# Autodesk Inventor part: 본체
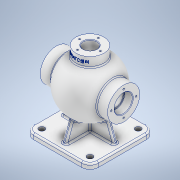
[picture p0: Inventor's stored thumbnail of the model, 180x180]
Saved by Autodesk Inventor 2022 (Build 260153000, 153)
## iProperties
Created: 2024-04
Part Number: 본체
Material: 알루미늄 6061
Document SubType Name: Modeling
Designer: Admin
Mass: 1526.53 g
Surface Area: 1174.37 cm^2
Volume: 565.38 cm^3
Density: 2.7 g/cm^3
Appearance: 알루미늄 - 평지
Author: Admin
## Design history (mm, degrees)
sketch "스케치1"
  geometry: L1 (-75.6, 0)-(75.6, 0) reference; L2 (0, -10.8)-(0, 64.8) reference; L3 (-54, 0)-(54, 0); A1 r 54 centre (0, 0) between (54, 0) and (-54, 0); 1 further point
  constraints: 2 end point, 2 point on circle, 1 centre point, 1 coincident, 1 horizontal, 1 symmetric about line
  dimensions: "d7" = 54 radius of A1; "d11" = 108 distance of L3.start L3.end
revolve "회전1" sketch "스케치1" stored, may be unused: angle "d9" = 90 deg
node "작업 평면2"
sketch "스케치2"
  geometry: C1 r 31 at (0, 0); 1 further point
  constraints: 1 centre point, 1 coincident
  dimensions: "d13" = 62 diameter of C1
extrude "돌출1" join sketch "스케치2" stored distance "d14" = 10; taper "d15" = 0 deg
node "작업 평면3"
sketch "스케치3"
  geometry: L1 (62.5, -62.5)-(-62.5, -62.5); L2 (-62.5, -62.5)-(-62.5, 62.5); L3 (-62.5, 62.5)-(62.5, 62.5); L4 (62.5, 62.5)-(62.5, -62.5); L5 (62.5, -62.5)-(-62.5, 62.5); L6 (-62.5, -62.5)-(62.5, 62.5); 1 further point
  constraints: 12 end point, 2 midpoint, 2 parallel, 1 horizontal, 1 perpendicular
  dimensions: "d17" = 125 distance of L2.end L3.end; "d18" = 125 distance of L1.end L2.end
extrude "돌출2" join sketch "스케치3" distance "d19" = 10; taper "d20" = 0 deg
sketch "스케치4"
  geometry: L1 (-112.8, 0)-(81.8, 0) reference; L2 (0, -87.5)-(0, 87.5) reference; L3 (-75, -50.5)-(0, -23.202); L4 (0, -23.202)-(0, 23.202); L5 (0, 23.202)-(-75, 50.5); L6 (-75, 62.5)-(-75, -62.5) reference; L7 (-85, -62.5)-(-75, -62.5) reference; L8 (-75, -50.5)-(-75, 50.5); 1 further point
  constraints: 8 end point, 2 point on line, 1 collinear, 1 midpoint, 1 vertical, 1 other
  dimensions: "d21" = 12 distance of L3.start L6.end; "d23" = 20 deg angle of L7 L3
extrude "돌출3" join sketch "스케치4" stored distance "d24" = 8; taper "d25" = 0 deg
sketch "스케치5"
  geometry: L1 (-91, 0)-(91, 0) reference; L2 (0, -112.8)-(0, 81.8) reference; L3 (50.5, -75)-(23.202, 0); L4 (23.202, 0)-(-23.202, 0); L5 (-23.202, 0)-(-50.5, -75); L6 (-62.5, -75)-(62.5, -75) reference; L7 (62.5, -85)-(62.5, -75) reference; L8 (50.5, -75)-(-50.5, -75); 1 further point
  constraints: 8 end point, 2 point on line, 1 collinear, 1 horizontal, 1 midpoint, 1 other
  dimensions: "d26" = 20 deg angle of L7 L3; "d27" = 12 distance of L6.end L3.start
extrude "돌출4" join sketch "스케치5" stored distance "d28" = 8; taper "d29" = 0 deg
sketch "스케치6"
  geometry: L1 (-91, 0)-(91, 0) reference; L2 (0, -112.8)-(0, 81.8) reference; L3 (44, 0)-(-44, 0); L4 (-44.215, -31)-(-44.215, 31) reference; A1 r 44 centre (0, 0) between (44, 0) and (-44, 0); 1 further point
  constraints: 2 end point, 2 point on circle, 2 point on line, 1 centre point, 1 coincident, 1 perpendicular, 1 symmetric about line
  dimensions: "d30" = 44 radius of A1
revolve "회전2" sketch "스케치6" stored, may be unused: angle "d31" = 90 deg
sketch "스케치7"
  geometry: C1 r 17.5 at (0, 0); 1 further point
  constraints: 1 centre point, 1 coincident
  dimensions: "d32" = 35 diameter of C1
extrude "돌출5" cut sketch "스케치7" distance "d33" = 16; taper "d34" = 0 deg
sketch "스케치8"
  geometry: C1 r 15 at (0, 0); 1 further point
  constraints: 1 centre point, 1 coincident
  dimensions: "d35" = 30 diameter of C1
extrude "돌출6" cut sketch "스케치8" stored distance "d36" = 16; taper "d37" = 0 deg
node "작업 평면7"
sketch "스케치9"
  geometry: C1 r 27 at (0, 0); 1 further point
  constraints: 1 centre point, 1 coincident
  dimensions: "d41" = 54 diameter of C1
extrude "돌출7" join sketch "스케치9" stored distance "d42" = 10; taper "d43" = 0 deg
sketch "스케치10"
  geometry: C1 r 13 at (0, 0); 1 further point
  constraints: 1 centre point, 1 coincident
  dimensions: "d44" = 26 diameter of C1
extrude "돌출8" cut sketch "스케치10" stored distance "d45" = 10; taper "d46" = 0 deg
sketch "스케치11"
  geometry: L1 (-91, 0)-(91, 0) reference; L2 (-4, -50.5)-(-4, -4) reference; L3 (-4, 37.329)-(-4, 4) reference; 7 further points
  constraints: 4 point on line, 1 horizontal alignment, 1 symmetric about line, 1 other
  dimensions: "d47" = 40 distance of point (-4, 20) point (-4, -20); "d48" = 40 distance of point (20, 0) point (-20, 0)
hole "구멍1" sketch "스케치11" at (-4, -20), (20, 0), (-4, 20), (-20, 0) diameter "d49" = 3.242; stored, may be unused: countersink angle "d53" = 90 deg, drill point angle "d55" = 118 deg; dims "d50" = 9, "d51" = 4, "d52" = 2, "d54" = 11
sketch "스케치12"
  geometry: L1 (0, -115)-(0, 95) reference; L2 (87.5, 0)-(-87.5, 0) reference; 5 further points
  constraints: 4 point on line, 2 symmetric about line
  dimensions: "d56" = 48 distance of point (24, 0) point (-24, 0); "d57" = 48 distance of point (0, 24) point (0, -24)
hole "구멍2" sketch "스케치12" at (-24, 0), (0, -24), (24, 0), (0, 24) diameter "d58" = 3.242; stored, may be unused: countersink angle "d62" = 90 deg, drill point angle "d64" = 118 deg; dims "d59" = 12, "d60" = 4, "d61" = 2, "d63" = 15
fillet "모깎기1" dims "d65" = 16
fillet "모깎기2" dims "d66" = 3
sketch "스케치13"
  geometry: L1 (-91, 0)-(91, 0) reference; L2 (46.5, 62.5)-(-46.5, 62.5) reference; L3 (62.5, -46.5)-(62.5, 46.5) reference; L4 (-46.5, -62.5)-(46.5, -62.5) reference; L5 (-62.5, 46.5)-(-62.5, -46.5) reference; L6 (0, 62.5)-(0, -62.5); A1 r 16 centre (-46.5, 46.5) between (-46.5, 62.5) and (-62.5, 46.5) reference; A2 r 16 centre (46.5, 46.5) between (62.5, 46.5) and (46.5, 62.5) reference; A3 r 16 centre (46.5, -46.5) between (46.5, -62.5) and (62.5, -46.5) reference; A4 r 16 centre (-46.5, -46.5) between (-62.5, -46.5) and (-46.5, -62.5) reference; 5 further points
  constraints: 4 coincident, 2 end point, 2 midpoint
hole "구멍3" sketch "스케치13" at (-46.5, 46.5), (46.5, 46.5), (46.5, -46.5), (-46.5, -46.5) diameter "d71" = 11; stored, may be unused: countersink angle "d75" = 90 deg, drill point angle "d77" = 118 deg; dims "d72" = 12, "d73" = 4, "d74" = 2, "d76" = 15
fillet "모깎기3" dims "d78" = 3
fillet "모깎기4" dims "d79" = 3
chamfer "모따기1" distance "d80" = 1; stored, may be unused: second distance "d81" = 2, angle "d82" = 45 deg
fillet "모깎기5" dims "d83" = 3
fillet "모깎기6" dims "d84" = 3
fillet "모깎기7" dims "d85" = 3
fillet "모깎기8" dims "d86" = 0.6
node "작업 평면8"
sketch "스케치14"
  geometry: L1 (-27, 65)-(27, 65) reference; L2 (0, -115)-(0, 95) reference; 2 further points
  constraints: 1 point on line, 1 other
  dimensions: "d88" = 9 distance from line of L1 point (0, 56)
feature "엠보싱1" sketch "스케치14" dims "d89" = 0.5, "d90" = 0
node "솔리드1"
mirror "미러1"
mirror "미러2"
mirror "미러3"
mirror "미러4"
node "투영된 루프1"
feature "A9D066F2-1C7D-4E18-AEED-F7BC21143FA4" dims "d71" = 11, "d72" = 12, "d73" = 4, "d74" = 2, "d75" = 90 deg, "d76" = 15, "d77" = 118 deg
other parameters: "d12" = 65, "d16" = -85, "d87" = 108.75
